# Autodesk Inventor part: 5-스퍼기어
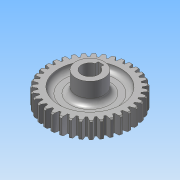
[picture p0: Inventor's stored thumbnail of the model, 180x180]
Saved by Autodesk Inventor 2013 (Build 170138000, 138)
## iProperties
Created: 2013-08
Part Number: 5-스퍼기어
Material: 강
Document SubType Name: Modeling
Designer: 한국산업디자인학원
Categories: <?xml version="1.0" encoding="UTF-16"?> <MemberInstance><Categories><FamilyTemplate><FamilyTemplateParameter ValueType="xs:double" Id="1" ObjectReferenceKey="da
Density: 1 g/cm^3
CustomPartVersion: 1
Author: 한국산업디자인학원
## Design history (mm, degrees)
sketch "Sketch1"
  geometry: C1 r 37 at (0, 0)
  constraints: 1 centre point
  dimensions: "d0" = 74 diameter of C1 (= da_da)
extrude "Extrusion1" new body sketch "Sketch1" distance "d1" = 15 (= da_b); taper "d2" = 0 deg
chamfer "모따기1" distance "d49" = 1; stored, may be unused: second distance "d50" = 2, angle "d51" = 45 deg
workplane "Work Plane2"
feature "피치 지름" dims "d4" = 10, "d5" = 0
workplane "Work Plane8"
workplane "Work Plane9"
feature "스퍼 기어" dims "da_b" = 15, "da_d" = 70, "da_aw" = 70, "da_da" = 74, "da_df" = 65, "da_dw" = 70, angle "da_beta" = 0 deg, "da_lefttooth" = 0, "da_righttooth" = 0
node "작업 평면11"
sketch "스케치6"
  geometry: C1 r 27.5 at (0, 0); A1 r 32.5 centre (0, 0) between (9.347, 31.127) and (7.941, 31.515) reference
  constraints: 1 centre point, 1 coincident
  dimensions: "d63" = 55 diameter of C1
extrude "돌출3" cut sketch "스케치6" distance "d65" = 5; taper "d66" = 0 deg
node "작업 평면12"
sketch "스케치3"
  geometry: C1 r 12.5 at (0, 0); 1 further point
  constraints: 1 centre point, 1 coincident
  dimensions: "d57" = 25 diameter of C1
extrude "돌출2" join sketch "스케치3" distance "d59" = 31; taper "d60" = 0 deg
sketch "스케치7"
  geometry: L1 (2.5, 7.071)-(2.5, 9.8); L2 (2.5, 9.8)-(-2.5, 9.8); L3 (-2.5, 9.8)-(-2.5, 7.071); C1 r 12.5 at (0, 0) reference; A1 r 7.5 centre (0, 0) between (2.5, 7.071) and (-2.5, 7.071)
  constraints: 6 end point, 2 parallel, 2 point on circle, 1 centre point, 1 coincident, 1 perpendicular, 1 vertical
  dimensions: "d68" = 15 diameter of A1; "d70" = 5 distance of L1.end L2.end; "d71" = 17.3 dimension on A1 L2
extrude "돌출4" cut sketch "스케치7" stored distance "d72" = 5; taper "d73" = 0 deg
fillet "모깎기1" dims "d74" = 5
body "Solid1"
mirror "대칭1"
sketch "Sketch2"
  geometry: C1 r 37 at (0, 0) reference; C2 r 35 at (0, 0)
  constraints: 1 centre point, 1 coincident
  dimensions: "d3" = 70 diameter of C2 (= da_dw)
body "Srf1"
other parameters: "d17" = 0, "d34" = 0.8976 (computed from da_z), "d39" = 0, "d41" = 0, "d47" = 0, "d48" = 0, "d52" = 3, "d67" = -7.5
